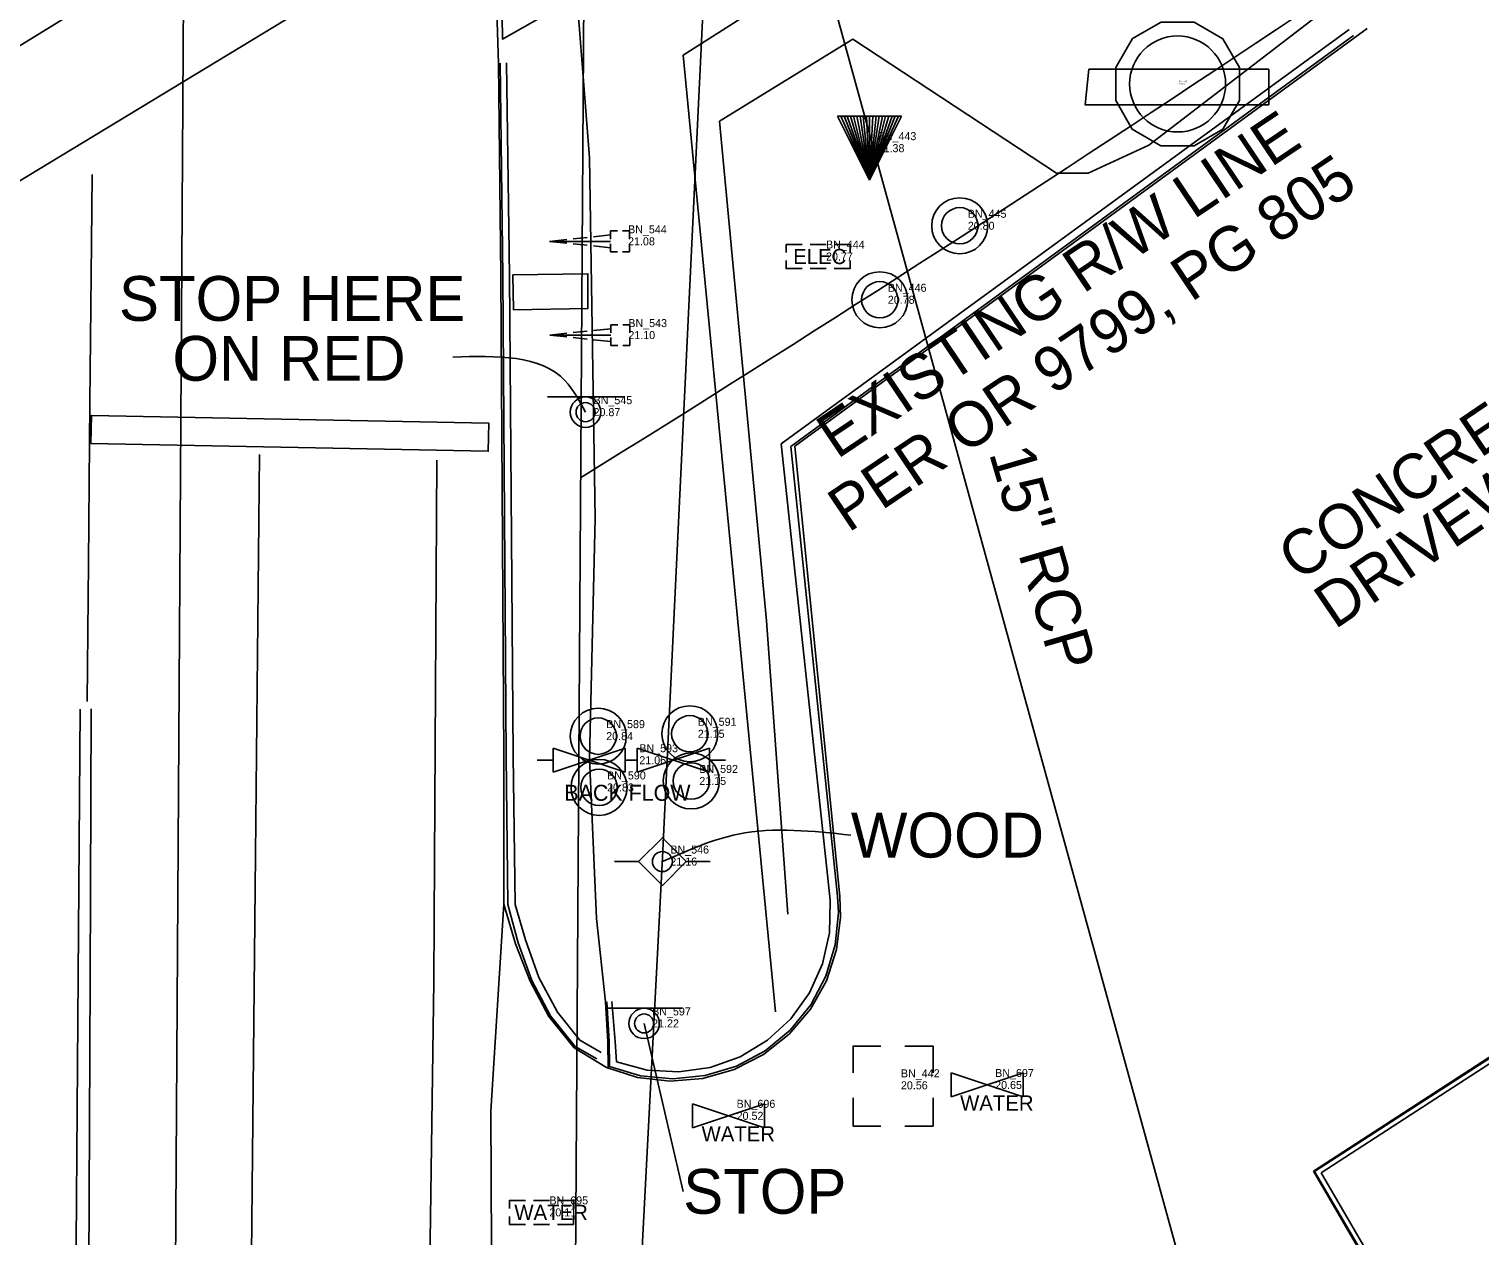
# Model space of a CAD drawing. Extents: x 509744 to 512285, y 1314862 to 1316822.
# Drawn here: x 510475.8 to 510566.4, y 1315825 to 1315900.5 of the extents above; entities that cross this region are included whole.
import ezdxf

# ---------------------------------------------------------------- set-up
doc = ezdxf.new("R2010")
doc.units = 0
for name, color, linetype in [('BaselineSurvey', 7, 'Continuous'), ('Bollard_ep', 7, 'Continuous'), ('CGBack_ep', 7, 'Continuous'), ('CGFace_ep', 7, 'Continuous'), ('CurbRampWarning_ep', 7, 'Continuous'), ('Driveway_ep', 7, 'Continuous'), ('ElecAer_ep', 7, 'Continuous'), ('Fence_ep', 7, 'Continuous'), ('GuardrailLt_ep', 7, 'Continuous'), ('MeterElec_ep', 7, 'Continuous'), ('MeterWater_ep', 7, 'Continuous'), ('NonPlottingEle_dp', 7, 'Continuous'), ('PavtAsphalt_ep', 7, 'Continuous'), ('PavtBreak_ep', 7, 'Continuous'), ('PipeCulvert_ep', 7, 'Continuous'), ('PMRK_ep', 7, 'Continuous'), ('PoleShared_ep', 7, 'Continuous'), ('PullBox_ep', 7, 'Continuous'), ('RailroadSgnalG_ep', 7, 'Continuous'), ('RailroadXing_ep', 7, 'Continuous'), ('RWLine_ep', 7, 'Continuous'), ('SidewalkBack_ep', 7, 'Continuous'), ('SignColumn_ep', 7, 'Continuous'), ('SignSingle_ep', 7, 'Continuous'), ('SignTrussOH_ep', 7, 'Continuous'), ('TextElevLabel', 7, 'Continuous'), ('TextNotes', 7, 'Continuous'), ('TextPtLabel', 7, 'Continuous'), ('TextTopoLabel_ep', 7, 'Continuous'), ('TextUtilLabel_ep', 7, 'Continuous'), ('Transformer_ep', 7, 'Continuous'), ('ValveBFP_ep', 7, 'Continuous'), ('ValveWater_ep', 7, 'Continuous')]:
    doc.layers.add(name, color=color, linetype=linetype)

msp = doc.modelspace()

# ---------------------------------------------------------------- linework, layer by layer
at = {"layer": 'BaselineSurvey'}
msp.add_line((510484.134, 1315694.907), (510491.264, 1316815.908), dxfattribs=at)
at = {"layer": 'Bollard_ep'}
for centre, radius in [((510533.947, 1315888.162), 1.75), ((510533.947, 1315888.162), 1.75), ((510533.947, 1315888.162), 1.137), ((510528.954, 1315883.538), 1.75), ((510528.954, 1315883.538), 1.75), ((510528.954, 1315883.538), 1.137), ((510511.364, 1315856.275), 1.75), ((510511.364, 1315856.275), 1.75), ((510517.086, 1315856.422), 1.75), ((510517.086, 1315856.422), 1.75), ((510517.086, 1315856.422), 1.137), ((510511.364, 1315856.275), 1.137), ((510511.416, 1315853.071), 1.75), ((510511.416, 1315853.071), 1.75), ((510517.177, 1315853.476), 1.75), ((510517.177, 1315853.476), 1.75), ((510511.416, 1315853.071), 1.137), ((510517.177, 1315853.476), 1.137)]:
    msp.add_circle(centre, radius, dxfattribs=at)
at = {"layer": 'CGBack_ep'}
for p, q in [((510522.786, 1315874.528), (510558.263, 1315900.433)), ((510505.83, 1315885.034), (510505.641, 1315898.348)), ((510525.824, 1315846.228), (510522.786, 1315874.528)), ((510592.462, 1315852.316), (510556.512, 1315828.995)), ((510556.512, 1315828.995), (510562.248, 1315819.203))]:
    msp.add_line(p, q, dxfattribs=at)
for points in [[(510505.83, 1315885.034), (510506.052, 1315855.036), (510506.177, 1315845.763)], [(510506.177, 1315845.763), (510506.815, 1315843.541), (510507.657, 1315841.187), (510508.814, 1315839.022), (510510.209, 1315837.276), (510511.557, 1315836.517)], [(510512.5, 1315835.927), (510514.418, 1315835.415), (510516.4, 1315835.296), (510518.365, 1315835.576), (510520.235, 1315836.244), (510521.934, 1315837.272), (510523.393, 1315838.619), (510524.554, 1315840.23), (510525.37, 1315842.041), (510525.807, 1315843.978), (510525.849, 1315845.963), (510525.824, 1315846.228)], [(510512.211, 1315839.695), (510512.416, 1315837.201), (510512.5, 1315835.927)]]:
    msp.add_lwpolyline(points, dxfattribs=at)
at = {"layer": 'CGFace_ep'}
for p, q in [((510523.402, 1315874.379), (510558.546, 1315900.04)), ((510505.415, 1315885.032), (510505.234, 1315898.317)), ((510526.309, 1315846.271), (510523.402, 1315874.379)), ((510592.314, 1315852.545), (510556.112, 1315829.073)), ((510556.112, 1315829.073), (510561.797, 1315819.397))]:
    msp.add_line(p, q, dxfattribs=at)
for points in [[(510505.415, 1315885.032), (510505.606, 1315855.034), (510505.712, 1315845.767)], [(510505.712, 1315845.767), (510506.356, 1315843.36), (510507.207, 1315841.008), (510508.382, 1315838.803), (510509.928, 1315836.882), (510511.277, 1315836.123)], [(510512.067, 1315835.644), (510514.011, 1315835.057), (510516.032, 1315834.86), (510518.053, 1315835.063), (510519.996, 1315835.657), (510521.786, 1315836.619), (510523.353, 1315837.912), (510524.637, 1315839.487), (510525.589, 1315841.282), (510526.172, 1315843.229), (510526.364, 1315845.251), (510526.309, 1315846.271)], [(510511.9, 1315839.683), (510512.047, 1315837.187), (510512.067, 1315835.644)]]:
    msp.add_lwpolyline(points, dxfattribs=at)
at = {"layer": 'CurbRampWarning_ep'}
for points in [[(510509.478, 1315905.488), (510509.761, 1315902.311), (510505.375, 1315899.825), (510505.338, 1315902.725)], [(510506.036, 1315885.096), (510510.719, 1315885.166), (510510.717, 1315883.004), (510506.066, 1315882.914)]]:
    msp.add_lwpolyline(points, close=True, dxfattribs=at)
at = {"layer": 'Driveway_ep'}
for p, q in [((510523.646, 1315874.385), (510559.387, 1315900.482)), ((510526.454, 1315846.253), (510523.646, 1315874.385)), ((510592.286, 1315852.589), (510556.043, 1315829.1)), ((510556.043, 1315829.1), (510561.698, 1315819.411))]:
    msp.add_line(p, q, dxfattribs=at)
for points in [[(510505.467, 1315845.769), (510504.651, 1315832.848), (510504.89, 1315785.958), (510507.589, 1315785.989)], [(510505.467, 1315845.769), (510506.19, 1315843.294), (510507.11, 1315840.97), (510508.289, 1315838.756), (510509.868, 1315836.797), (510511.875, 1315835.578)], [(510511.875, 1315835.578), (510513.823, 1315834.957), (510515.855, 1315834.726), (510517.893, 1315834.893), (510519.86, 1315835.453), (510521.681, 1315836.385), (510523.287, 1315837.652), (510524.616, 1315839.207), (510525.618, 1315840.991), (510526.255, 1315842.935), (510526.503, 1315844.965), (510526.454, 1315846.253)]]:
    msp.add_lwpolyline(points, dxfattribs=at)
at = {"layer": 'ElecAer_ep'}
msp.add_lwpolyline([(510545.674, 1315586.019), (510506.94, 1315686.686), (510515.37, 1315848.689), (510519.717, 1315939.401)], dxfattribs=at)
at = {"layer": 'Fence_ep'}
msp.add_lwpolyline([(510688.979, 1316027.037), (510652.223, 1315995.496), (510596.64, 1315952.428), (510538.573, 1315912.772), (510516.68, 1315898.832), (510522.427, 1315839.044)], dxfattribs=at)
at = {"layer": 'GuardrailLt_ep'}
msp.add_lwpolyline([(510523.206, 1315845.16), (510521.878, 1315863.489), (510518.931, 1315894.696), (510527.269, 1315899.818), (510539.994, 1315891.448), (510541.97, 1315891.448), (510545.754, 1315893.189), (510557.038, 1315901.861)], dxfattribs=at)
at = {"layer": 'MeterElec_ep'}
for points in [[(510523.094, 1315886.49), (510523.094, 1315886.992), (510524.094, 1315886.992)], [(510524.594, 1315886.992), (510525.594, 1315886.992)], [(510526.094, 1315886.992), (510527.094, 1315886.992), (510527.094, 1315886.49)], [(510524.094, 1315885.488), (510523.094, 1315885.488), (510523.094, 1315885.99)], [(510527.094, 1315885.99), (510527.094, 1315885.488), (510526.094, 1315885.488)], [(510525.594, 1315885.488), (510524.594, 1315885.488)]]:
    msp.add_lwpolyline(points, dxfattribs=at)
at = {"layer": 'MeterWater_ep'}
for points in [[(510505.814, 1315826.769), (510505.814, 1315827.271), (510506.814, 1315827.271)], [(510507.314, 1315827.271), (510508.314, 1315827.271)], [(510508.814, 1315827.271), (510509.814, 1315827.271), (510509.814, 1315826.769)], [(510506.814, 1315825.767), (510505.814, 1315825.767), (510505.814, 1315826.269)], [(510509.814, 1315826.269), (510509.814, 1315825.767), (510508.814, 1315825.767)], [(510508.314, 1315825.767), (510507.314, 1315825.767)]]:
    msp.add_lwpolyline(points, dxfattribs=at)
at = {"layer": 'PavtAsphalt_ep'}
for points in [[(510505.272, 1315885.031), (510505.144, 1315898.311), (510504.983, 1315902.886), (510509.755, 1315906.053), (510509.25, 1315911.598)], [(510505.272, 1315885.031), (510505.467, 1315855.034), (510505.467, 1315845.769)]]:
    msp.add_lwpolyline(points, dxfattribs=at)
at = {"layer": 'PavtBreak_ep'}
msp.add_lwpolyline([(510479.751, 1315891.372), (510479.711, 1315887.097), (510479.615, 1315877.098), (510479.52, 1315867.098), (510479.438, 1315858.444)], dxfattribs=at)
at = {"layer": 'PipeCulvert_ep'}
msp.add_line((510502.341, 1315988.248), (510563.442, 1315766.288), dxfattribs=at)
at = {"layer": 'PMRK_ep'}
msp.add_lwpolyline([(510479.671, 1315874.564), (510504.493, 1315874.08), (510504.528, 1315875.83), (510479.706, 1315876.313)], close=True, dxfattribs=at)
for points in [[(510490.21, 1315873.872), (510489.961, 1315848.874), (510489.712, 1315823.876), (510489.464, 1315798.877), (510489.446, 1315797.036), (510489.419, 1315772.036), (510489.4, 1315753.711), (510489.424, 1315728.711), (510489.433, 1315720.259)], [(510501.274, 1315873.524), (510501.14, 1315848.525), (510501.1, 1315840.936), (510500.739, 1315815.938), (510500.622, 1315807.881), (510500.483, 1315782.881), (510500.407, 1315769.216), (510500.319, 1315744.217), (510500.231, 1315719.217), (510500.143, 1315694.217), (510500.163, 1315678.23)], [(510478.996, 1315857.956), (510478.816, 1315832.957), (510478.635, 1315807.957), (510478.504, 1315789.892), (510478.455, 1315764.892), (510478.44, 1315757.169), (510478.392, 1315732.169), (510478.36, 1315716.004), (510477.993, 1315703.823), (510480.36, 1315707.039), (510483.335, 1315713.774), (510486.266, 1315722.878), (510487.222, 1315729.873), (510487.243, 1315735.827), (510486.939, 1315740.889), (510485.615, 1315749.384), (510484.008, 1315761.16), (510482.336, 1315772.048), (510480.959, 1315782.067), (510479.686, 1315791.325), (510479.445, 1315798.02), (510479.55, 1315823.02), (510479.625, 1315841.097), (510479.696, 1315857.979)]]:
    msp.add_lwpolyline(points, dxfattribs=at)
at = {"layer": 'PoleShared_ep'}
for p, q in [((510512.383, 1315848.439), (510513.883, 1315848.439)), ((510518.358, 1315848.439), (510516.858, 1315848.439))]:
    msp.add_line(p, q, dxfattribs=at)
msp.add_lwpolyline([(510513.883, 1315848.439), (510515.37, 1315849.927), (510516.858, 1315848.439), (510515.37, 1315846.951), (510513.883, 1315848.439)], dxfattribs=at)
msp.add_circle((510515.37, 1315848.439), 0.625, dxfattribs=at)
at = {"layer": 'PullBox_ep'}
for points in [[(510529.019, 1315836.908), (510527.285, 1315836.908), (510527.285, 1315835.232)], [(510532.28, 1315835.232), (510532.28, 1315836.908), (510530.519, 1315836.908)], [(510527.285, 1315833.68), (510527.285, 1315831.908)], [(510530.519, 1315831.908), (510532.28, 1315831.908), (510532.28, 1315833.68)], [(510527.285, 1315831.908), (510529.019, 1315831.908)]]:
    msp.add_lwpolyline(points, dxfattribs=at)
at = {"layer": 'RailroadSgnalG_ep'}
for p, q in [((510509.794, 1315887.344), (510510.663, 1315887.436)), ((510511.061, 1315887.478), (510512.128, 1315887.59)), ((510512.128, 1315887.336), (510512.128, 1315887.84)), ((510512.128, 1315887.84), (510512.578, 1315887.84)), ((510513.328, 1315887.84), (510512.878, 1315887.84)), ((510513.328, 1315887.84), (510513.328, 1315887.336)), ((510508.328, 1315887.19), (510509.396, 1315887.302)), ((510508.328, 1315887.19), (510509.396, 1315887.078)), ((510508.328, 1315887.19), (510512.128, 1315887.19)), ((510509.794, 1315887.036), (510510.663, 1315886.944)), ((510511.061, 1315886.902), (510512.128, 1315886.79)), ((510512.128, 1315886.54), (510512.128, 1315887.036)), ((510512.128, 1315886.54), (510512.578, 1315886.54)), ((510512.878, 1315886.54), (510513.328, 1315886.54)), ((510513.328, 1315886.54), (510513.328, 1315887.036)), ((510508.344, 1315881.332), (510509.412, 1315881.444)), ((510508.344, 1315881.332), (510509.412, 1315881.219)), ((510508.344, 1315881.332), (510512.144, 1315881.332)), ((510509.809, 1315881.486), (510510.678, 1315881.577)), ((510509.809, 1315881.177), (510510.678, 1315881.086)), ((510511.076, 1315881.619), (510512.144, 1315881.732)), ((510512.144, 1315881.478), (510512.144, 1315881.982)), ((510512.144, 1315881.982), (510512.594, 1315881.982)), ((510512.144, 1315880.682), (510512.144, 1315881.178)), ((510513.344, 1315881.982), (510512.894, 1315881.982)), ((510513.344, 1315881.982), (510513.344, 1315881.478)), ((510513.344, 1315880.682), (510513.344, 1315881.178)), ((510511.076, 1315881.044), (510512.144, 1315880.932)), ((510512.144, 1315880.682), (510512.594, 1315880.682)), ((510512.894, 1315880.682), (510513.344, 1315880.682))]:
    msp.add_line(p, q, dxfattribs=at)
at = {"layer": 'RailroadXing_ep'}
msp.add_lwpolyline([(510510.582, 1315921.202), (510512.01, 1315919.228), (510509.816, 1315917.634), (510511.971, 1315913.247), (510456.241, 1315879.479), (510455.173, 1315881.471), (510457.955, 1315883.273), (510455.55, 1315887.297)], close=True, dxfattribs=at)
at = {"layer": 'RWLine_ep'}
msp.add_line((510509.14, 1315695.788), (510510.666, 1315935.625), dxfattribs=at)
msp.add_arc((509687.45, 1317196.75), 1559.13, 301.852815, 305.538964, dxfattribs=at)
at = {"layer": 'SidewalkBack_ep'}
msp.add_lwpolyline([(510509.755, 1315906.053), (510510.817, 1315892.397), (510511.169, 1315869.896), (510510.821, 1315854.873), (510511.246, 1315844.882), (510511.81, 1315839.68), (510511.968, 1315837.184), (510511.99, 1315835.53)], dxfattribs=at)
at = {"layer": 'SignColumn_ep'}
msp.add_line((510547.554, 1315897.022), (510547.554, 1315897.022), dxfattribs=at)
msp.add_lwpolyline([(510551.416, 1315895.982), (510551.419, 1315898.053), (510550.386, 1315899.847), (510548.594, 1315900.884), (510546.523, 1315900.887), (510544.729, 1315899.853), (510543.691, 1315898.061), (510543.689, 1315895.991), (510544.722, 1315894.197), (510546.514, 1315893.159), (510548.585, 1315893.157), (510550.379, 1315894.19)], close=True, dxfattribs=at)
msp.add_circle((510547.554, 1315897.022), 3, dxfattribs=at)
at = {"layer": 'SignSingle_ep'}
for p, q in [((510508.196, 1315877.467), (510512.946, 1315877.467)), ((510511.856, 1315839.276), (510516.606, 1315839.276))]:
    msp.add_line(p, q, dxfattribs=at)
for centre, radius in [((510510.571, 1315876.517), 0.95), ((510510.571, 1315876.517), 0.594), ((510514.231, 1315838.326), 0.95), ((510514.231, 1315838.326), 0.594)]:
    msp.add_circle(centre, radius, dxfattribs=at)
at = {"layer": 'SignTrussOH_ep'}
msp.add_lwpolyline([(510542.01, 1315897.941), (510553.251, 1315897.941), (510553.251, 1315895.725), (510541.777, 1315895.725)], close=True, dxfattribs=at)
at = {"layer": 'TextTopoLabel_ep'}
msp.add_line((510514.231, 1315838.326), (510516.673, 1315827.835), dxfattribs=at)
msp.add_spline([(510502.289, 1315879.963), (510509.306, 1315878.473), (510510.571, 1315876.517)], degree=3, dxfattribs=at)
at = {"layer": 'TextUtilLabel_ep'}
msp.add_spline([(510515.37, 1315848.439), (510520.102, 1315850.15), (510527.146, 1315850.089)], degree=3, dxfattribs=at)
at = {"layer": 'Transformer_ep'}
for p, q in [((510528.318, 1315891.011), (510526.318, 1315895.011)), ((510526.318, 1315895.011), (510530.318, 1315895.011)), ((510526.517, 1315895.011), (510528.318, 1315891.011)), ((510528.318, 1315891.011), (510526.717, 1315895.011)), ((510528.318, 1315891.011), (510526.916, 1315895.011)), ((510528.318, 1315891.011), (510527.119, 1315895.011)), ((510528.318, 1315891.011), (510527.318, 1315895.011)), ((510528.318, 1315891.011), (510527.517, 1315895.011)), ((510528.318, 1315891.011), (510527.717, 1315895.011)), ((510528.318, 1315891.011), (510527.92, 1315895.011)), ((510528.318, 1315891.011), (510528.119, 1315895.011)), ((510528.318, 1315891.011), (510528.517, 1315895.011)), ((510528.318, 1315891.011), (510528.717, 1315895.011)), ((510528.318, 1315891.011), (510528.916, 1315895.011)), ((510528.318, 1315891.011), (510529.119, 1315895.011)), ((510528.318, 1315891.011), (510529.517, 1315895.011)), ((510528.318, 1315891.011), (510529.721, 1315895.011)), ((510528.318, 1315891.011), (510529.916, 1315895.011)), ((510528.318, 1315891.011), (510530.115, 1315895.011)), ((510530.318, 1315895.011), (510528.318, 1315891.011)), ((510528.318, 1315891.011), (510528.318, 1315895.011)), ((510528.318, 1315891.011), (510529.318, 1315895.011))]:
    msp.add_line(p, q, dxfattribs=at)
at = {"layer": 'ValveBFP_ep'}
for p, q in [((510513.055, 1315854.021), (510508.555, 1315855.521)), ((510508.555, 1315854.021), (510513.055, 1315855.521)), ((510508.555, 1315854.021), (510508.555, 1315855.521)), ((510513.055, 1315855.521), (510513.055, 1315854.021)), ((510518.305, 1315854.021), (510513.805, 1315855.521)), ((510513.805, 1315854.021), (510518.305, 1315855.521)), ((510513.805, 1315854.021), (510513.805, 1315855.521)), ((510518.305, 1315855.521), (510518.305, 1315854.021)), ((510507.555, 1315854.771), (510508.555, 1315854.771)), ((510513.055, 1315854.771), (510513.805, 1315854.771)), ((510518.305, 1315854.771), (510519.305, 1315854.771))]:
    msp.add_line(p, q, dxfattribs=at)
at = {"layer": 'ValveWater_ep'}
for p, q in [((510537.908, 1315833.731), (510533.408, 1315835.231)), ((510533.408, 1315833.731), (510537.908, 1315835.231)), ((510533.408, 1315833.731), (510533.408, 1315835.231)), ((510537.908, 1315835.231), (510537.908, 1315833.731)), ((510521.759, 1315831.803), (510517.259, 1315833.303)), ((510517.259, 1315831.803), (510521.759, 1315833.303)), ((510517.259, 1315831.803), (510517.259, 1315833.303)), ((510521.759, 1315833.303), (510521.759, 1315831.803))]:
    msp.add_line(p, q, dxfattribs=at)

# ---------------------------------------------------------------- texts
at = {"layer": 'MeterElec_ep'}
msp.add_text('ELEC', height=0.95, dxfattribs=at).set_placement((510523.542, 1315885.767))
at = {"layer": 'MeterWater_ep'}
msp.add_text('WATER', height=0.95, dxfattribs=at).set_placement((510506.125, 1315826.046))
at = {"layer": 'NonPlottingEle_dp'}
msp.add_text('15" RCP', height=2.8, rotation=286.24276, dxfattribs=at).set_placement((510535.761, 1315873.96))
at = {"layer": 'TextElevLabel'}
for s, height, p in [('21.16', 0.1, (510547.654, 1315896.972)), ('21.38', 0.5, (510528.818, 1315892.761)), ('20.80', 0.5, (510534.447, 1315887.912)), ('21.08', 0.5, (510513.228, 1315886.94)), ('20.77', 0.5, (510525.594, 1315885.992)), ('20.78', 0.5, (510529.454, 1315883.288)), ('21.10', 0.5, (510513.244, 1315881.082)), ('20.87', 0.5, (510511.071, 1315876.267)), ('21.15', 0.5, (510517.586, 1315856.172)), ('20.84', 0.5, (510511.864, 1315856.025)), ('21.06', 0.5, (510513.93, 1315854.521)), ('20.83', 0.5, (510511.916, 1315852.821)), ('21.15', 0.5, (510517.677, 1315853.226)), ('21.16', 0.5, (510515.87, 1315848.189)), ('21.22', 0.5, (510514.731, 1315838.076)), ('20.56', 0.5, (510530.273, 1315834.208)), ('20.65', 0.5, (510536.158, 1315834.231)), ('20.52', 0.5, (510520.009, 1315832.303)), ('20.11', 0.5, (510508.314, 1315826.269))]:
    msp.add_text(s, height=height, dxfattribs=at).set_placement(p)
at = {"layer": 'TextNotes'}
for s, p in [('EXISTING R/W LINE ', (510526.286, 1315873.543)), ('PER OR 9799, PG 805', (510526.987, 1315868.952))]:
    msp.add_text(s, height=2.8, rotation=33.94179, dxfattribs=at).set_placement(p)
at = {"layer": 'TextPtLabel'}
for s, height, p in [('BN_447', 0.1, (510547.654, 1315897.122)), ('BN_443', 0.5, (510528.818, 1315893.511)), ('BN_445', 0.5, (510534.447, 1315888.662)), ('BN_544', 0.5, (510513.228, 1315887.69)), ('BN_444', 0.5, (510525.594, 1315886.742)), ('BN_446', 0.5, (510529.454, 1315884.038)), ('BN_543', 0.5, (510513.244, 1315881.832)), ('BN_545', 0.5, (510511.071, 1315877.017)), ('BN_589', 0.5, (510511.864, 1315856.775)), ('BN_591', 0.5, (510517.586, 1315856.922)), ('BN_593', 0.5, (510513.93, 1315855.271)), ('BN_590', 0.5, (510511.916, 1315853.571)), ('BN_592', 0.5, (510517.677, 1315853.976)), ('BN_546', 0.5, (510515.87, 1315848.939)), ('BN_597', 0.5, (510514.731, 1315838.826)), ('BN_442', 0.5, (510530.273, 1315834.958)), ('BN_697', 0.5, (510536.158, 1315834.981)), ('BN_696', 0.5, (510520.009, 1315833.053)), ('BN_695', 0.5, (510508.314, 1315827.019))]:
    msp.add_text(s, height=height, dxfattribs=at).set_placement(p)
at = {"layer": 'TextTopoLabel_ep'}
for s, p in [('STOP HERE', (510481.43, 1315882.221)), ('ON RED', (510484.768, 1315878.481)), ('WOOD', (510527.146, 1315848.689)), ('STOP', (510516.673, 1315826.435))]:
    msp.add_text(s, height=2.8, dxfattribs=at).set_placement(p)
for s, p in [('CONCRETE', (510555.114, 1315865.892)), ('DRIVEWAY', (510557.375, 1315862.907))]:
    msp.add_text(s, height=2.8, rotation=34.22564, dxfattribs=at).set_placement(p)
at = {"layer": 'ValveBFP_ep'}
msp.add_text('BACK FLOW', height=1, dxfattribs=at).set_placement((510509.251, 1315852.236))
at = {"layer": 'ValveWater_ep'}
for p in [(510533.969, 1315832.881), (510517.82, 1315830.953)]:
    msp.add_text('WATER', height=0.95, dxfattribs=at).set_placement(p)

doc.saveas('drawing.dxf')
